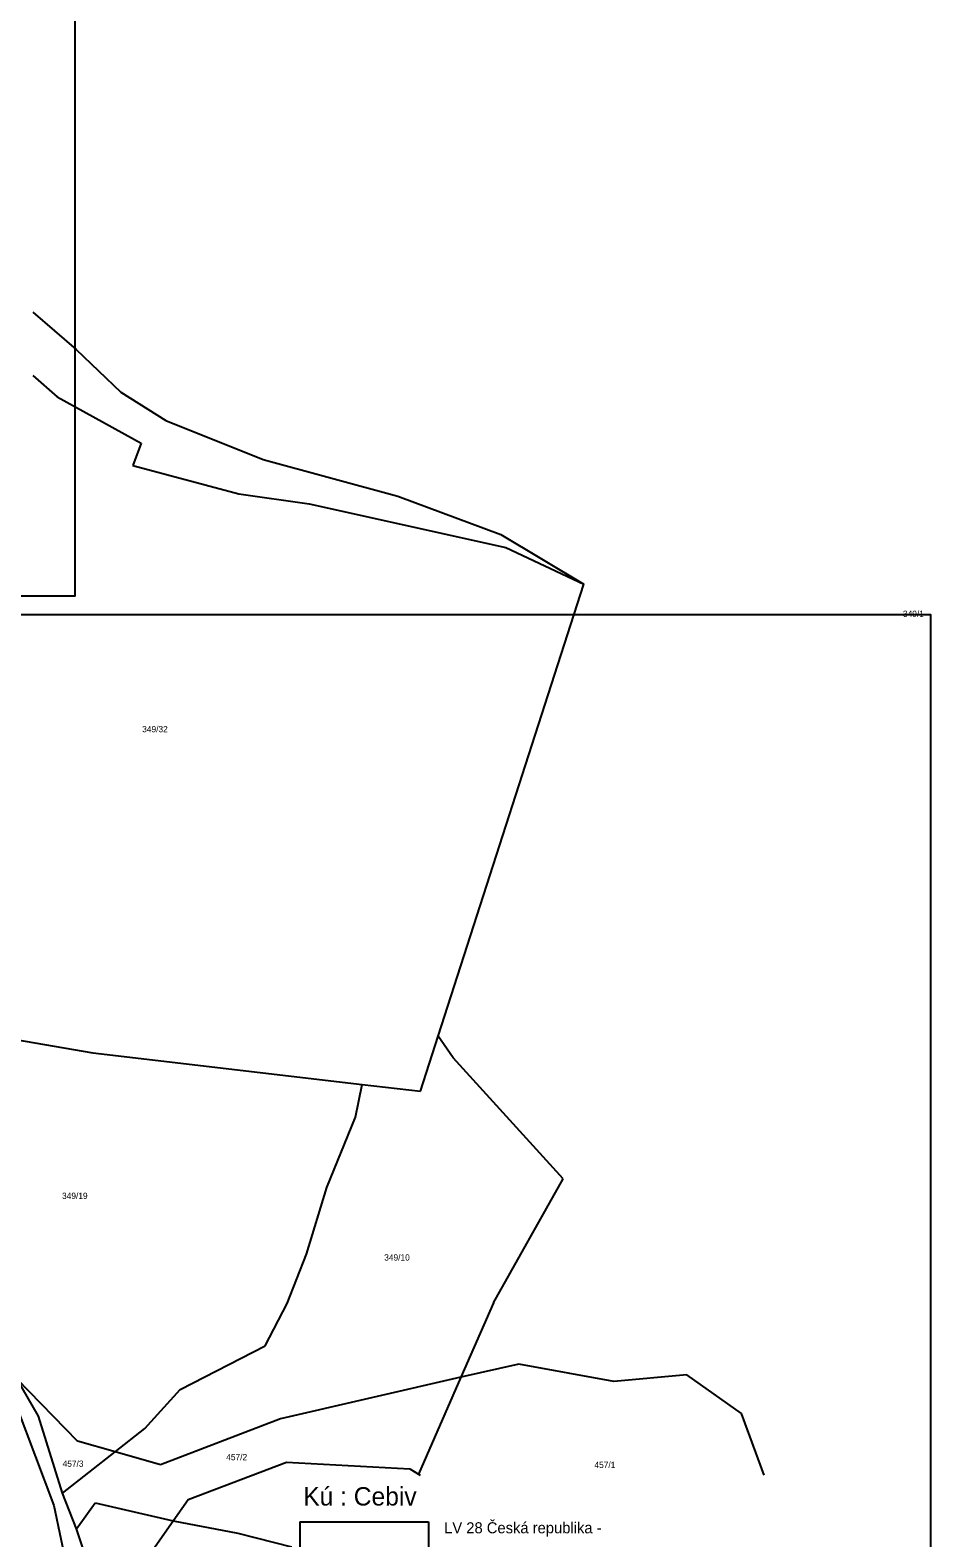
# Model space of a CAD drawing. Extents: x -852001 to -842497, y -1063614 to -1052182.
# Drawn here: x -848561.2 to -848316.3, y -1056881.4 to -1056471.5 of the extents above; entities that cross this region are included whole.
import ezdxf

# ---------------------------------------------------------------- set-up
doc = ezdxf.new("R2010")
doc.units = 0
for name, color, linetype in [('KN_HRANICE', 7, 'Continuous'), ('KN_PARCELY', 7, 'Continuous'), ('LEGENDA', 7, 'Continuous')]:
    doc.layers.add(name, color=color, linetype=linetype)

msp = doc.modelspace()

# ---------------------------------------------------------------- linework, layer by layer
at = {"layer": 'KN_HRANICE'}
for p, q in [((-848560.51, -1056548.13), (-848548.7, -1056558.28)), ((-848548.7, -1056558.28), (-848536.55, -1056569.87)), ((-848560.51, -1056565.33), (-848553.88, -1056571.19)), ((-848553.88, -1056571.19), (-848531.02, -1056583.78)), ((-848536.55, -1056569.87), (-848524.34, -1056577.58)), ((-848524.34, -1056577.58), (-848497.9, -1056588.24)), ((-848531.02, -1056583.78), (-848533.34, -1056589.85)), ((-848533.34, -1056589.85), (-848504.46, -1056597.52)), ((-848497.9, -1056588.24), (-848461.25, -1056598.19)), ((-848504.46, -1056597.52), (-848485.37, -1056600.27)), ((-848461.25, -1056598.19), (-848433.21, -1056608.61)), ((-848485.37, -1056600.27), (-848431.89, -1056612.13)), ((-848433.21, -1056608.61), (-848410.68, -1056622.09)), ((-848431.89, -1056612.13), (-848410.68, -1056622.09)), ((-848450.31, -1056745.03), (-848410.68, -1056622.09)), ((-848607.06, -1056738.68), (-848544.16, -1056749.48)), ((-848455.12, -1056759.96), (-848450.31, -1056745.03)), ((-848446.2, -1056750.86), (-848450.31, -1056745.03)), ((-848544.16, -1056749.48), (-848470.98, -1056758.09)), ((-848416.28, -1056783.8), (-848446.2, -1056750.86)), ((-848472.74, -1056767.05), (-848470.98, -1056758.09)), ((-848470.98, -1056758.09), (-848455.12, -1056759.96)), ((-848480.51, -1056786.14), (-848472.74, -1056767.05)), ((-848435.24, -1056817.46), (-848416.28, -1056783.8)), ((-848486.05, -1056804.27), (-848480.51, -1056786.14)), ((-848491.32, -1056817.68), (-848486.05, -1056804.27)), ((-848497.33, -1056829.21), (-848491.32, -1056817.68)), ((-848435.24, -1056817.46), (-848444.08, -1056837.72)), ((-848520.44, -1056841.09), (-848497.33, -1056829.21)), ((-848444.08, -1056837.72), (-848493.18, -1056849.04)), ((-848444.08, -1056837.72), (-848455.59, -1056864.1)), ((-848428.3, -1056834.19), (-848444.08, -1056837.72)), ((-848402.49, -1056838.87), (-848428.3, -1056834.19)), ((-848382.68, -1056837.09), (-848402.49, -1056838.87)), ((-848367.77, -1056847.54), (-848382.68, -1056837.09)), ((-848548.32, -1056855.1), (-848564.71, -1056838.24)), ((-848558.94, -1056848.34), (-848564.71, -1056838.24)), ((-848530.02, -1056851.64), (-848520.44, -1056841.09)), ((-848564.72, -1056846.14), (-848554.75, -1056872.56)), ((-848552.42, -1056869.27), (-848558.94, -1056848.34)), ((-848493.18, -1056849.04), (-848525.75, -1056861.53)), ((-848361.63, -1056864.35), (-848367.77, -1056847.54)), ((-848538.11, -1056858.01), (-848530.02, -1056851.64)), ((-848552.42, -1056869.27), (-848538.11, -1056858.01)), ((-848538.11, -1056858.01), (-848548.32, -1056855.1)), ((-848525.75, -1056861.53), (-848538.11, -1056858.01)), ((-848518.28, -1056870.94), (-848491.54, -1056860.78)), ((-848491.54, -1056860.78), (-848457.98, -1056862.66)), ((-848457.98, -1056862.66), (-848455.59, -1056864.1)), ((-848455.59, -1056864.1), (-848455.7, -1056864.35)), ((-848455.59, -1056864.1), (-848455.16, -1056864.35)), ((-848548.59, -1056878.97), (-848552.42, -1056869.27)), ((-848554.75, -1056872.56), (-848549.94, -1056895.74)), ((-848548.59, -1056878.97), (-848543.53, -1056871.86)), ((-848543.53, -1056871.86), (-848522.36, -1056876.75)), ((-848522.36, -1056876.75), (-848518.28, -1056870.94)), ((-848533.12, -1056892.09), (-848522.36, -1056876.75)), ((-848522.36, -1056876.75), (-848504.72, -1056880.07)), ((-848544.95, -1056889.68), (-848548.59, -1056878.97)), ((-848504.72, -1056880.07), (-848490.15, -1056883.83))]:
    msp.add_line(p, q, dxfattribs=at)
at = {"layer": 'LEGENDA'}
for q in [(-848452.86, -1056877.05), (-848487.86, -1056887.05)]:
    msp.add_line((-848487.86, -1056877.05), q, dxfattribs=at)
for points in [[(-849142.95, -1056625.24), (-848548.95, -1056625.24), (-848548.95, -1056205.24), (-849142.95, -1056205.24)], [(-848910.31, -1057050.45), (-848316.31, -1057050.45), (-848316.31, -1056630.45), (-848910.31, -1056630.45)]]:
    msp.add_lwpolyline(points, close=True, dxfattribs=at)
msp.add_lwpolyline([(-848452.86, -1056877.05), (-848452.86, -1056887.05), (-848487.86, -1056887.05)], dxfattribs=at)

# ---------------------------------------------------------------- texts
at = {"layer": 'KN_PARCELY'}
for s, p in [('349/1', (-848323.89, -1056631)), ('349/32', (-848530.75, -1056662.37)), ('349/19', (-848552.54, -1056789.25)), ('349/10', (-848464.94, -1056806)), ('457/3', (-848552.39, -1056862.07)), ('457/2', (-848507.9, -1056860.28)), ('457/1', (-848407.79, -1056862.4))]:
    msp.add_text(s, height=1.7, dxfattribs=at).set_placement(p)
at = {"layer": 'LEGENDA'}
for s, height, p in [('Kú : Cebiv', 5, (-848486.97, -1056872.6)), ('LV 28 Česká republika -', 3, (-848448.65, -1056880.15))]:
    msp.add_text(s, height=height, dxfattribs=at).set_placement(p)

doc.saveas('drawing.dxf')
